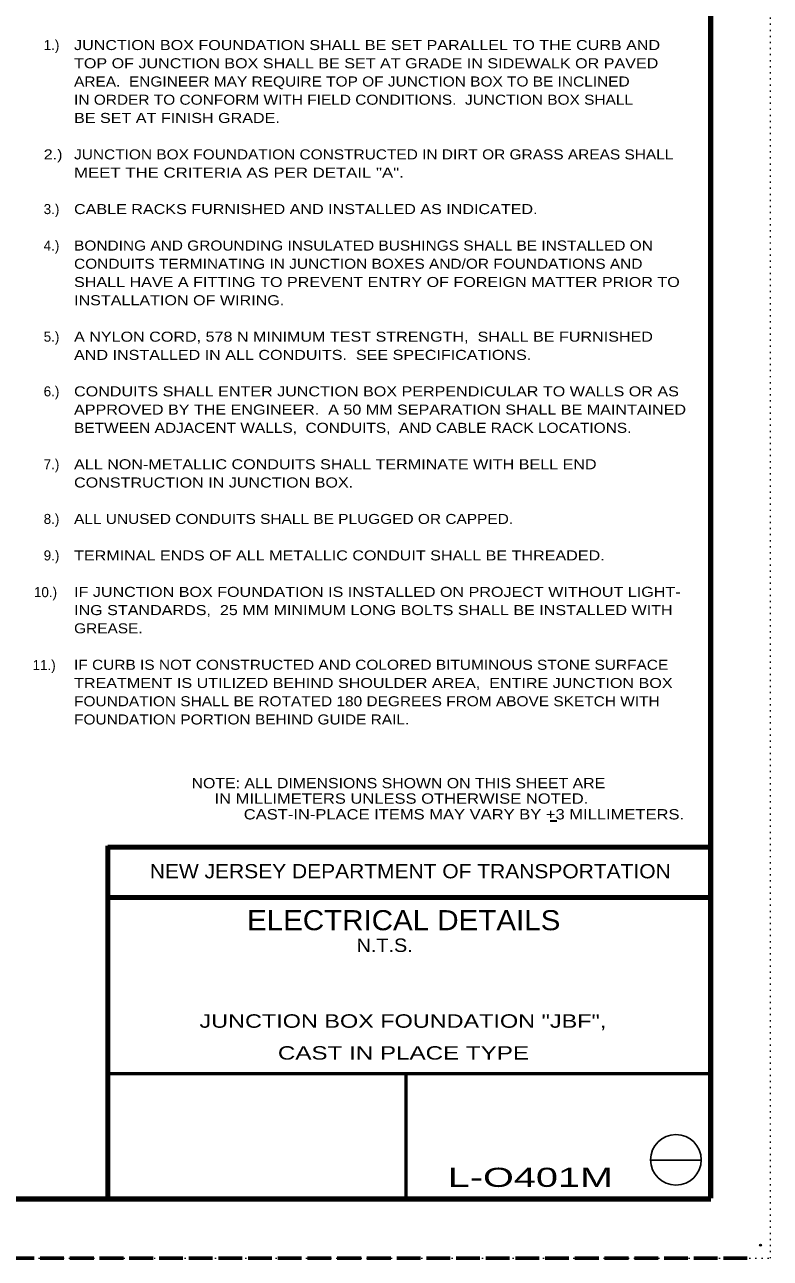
# Model space of a CAD drawing. Extents: x 312583 to 312854, y 144419 to 144597.
# Drawn here: x 312797 to 312853.5, y 144418.6 to 144512 of the extents above; entities that cross this region are included whole.
import ezdxf
from ezdxf.enums import TextEntityAlignment as Align

# ---------------------------------------------------------------- set-up
doc = ezdxf.new("R2010")
doc.units = 0
doc.header["$LTSCALE"] = 0.3
doc.header["$PDMODE"] = 32
doc.header["$PDSIZE"] = 0.15
doc.linetypes.add('DOTTED', pattern=[1.5, 0.3, -1.2])
doc.linetypes.add('LONG_DASHED', pattern=[7.5, 6, -1.5])
for name, color, linetype, lineweight in [('1', 7, 'Continuous', 13), ('10', 7, 'Continuous', 25), ('63', 7, 'DOTTED', 13)]:
    doc.layers.add(name, color=color, linetype=linetype, lineweight=lineweight)
doc.layers.add('2', color=7, linetype='Continuous')
doc.layers.add('5', color=7, linetype='Continuous')

msp = doc.modelspace()

# ---------------------------------------------------------------- linework, layer by layer
at = {"layer": '1', "lineweight": 158}
for p, q in [((312849, 144423.1446), (312849, 144585.0846)), ((312616.5, 144423.0846), (312849, 144423.0846))]:
    msp.add_line(p, q, dxfattribs=at)
at = {"layer": '1', "lineweight": 35}
msp.add_line((312836.8248, 144451.6973), (312837.3347, 144451.6973), dxfattribs=at)
at = {"layer": '1', "lineweight": 80}
for p, q in [((312803.31, 144423.1446), (312803.31, 144449.8146)), ((312803.31, 144449.7246), (312849, 144449.7246)), ((312803.31, 144445.9146), (312849, 144445.9146))]:
    msp.add_line(p, q, dxfattribs=at)
at = {"layer": '1', "lineweight": 53}
for p, q in [((312849, 144432.5546), (312803.2881, 144432.5546)), ((312825.881, 144432.5546), (312825.881, 144423.0843))]:
    msp.add_line(p, q, dxfattribs=at)
at = {"layer": '1', "linetype": 'LONG_DASHED', "lineweight": 60}
msp.add_line((312851.75, 144418.5846), (312583.526, 144418.5846), dxfattribs=at)
at = {"layer": '1'}
msp.add_point((312852.75, 144419.5846), dxfattribs=at)
at = {"layer": '10'}
msp.add_line((312844.4384, 144426.0259), (312848.2794, 144426.0259), dxfattribs=at)
msp.add_circle((312846.3494, 144426.0405), 1.9159, dxfattribs=at)
at = {"layer": '63'}
msp.add_lwpolyline([(312601.2, 144418.5846), (312853.5, 144418.5846), (312853.5, 144596.7846)], dxfattribs=at)

# ---------------------------------------------------------------- texts
at = {"layer": '1'}
for s, p in [('1.)', (312798.4647, 144510.0623)), ('3.)', (312798.4647, 144497.6423)), ('4.)', (312798.4647, 144494.8823)), ('5.)', (312798.4647, 144487.9823)), ('6.)', (312798.4647, 144483.8423)), ('7.)', (312798.4647, 144478.3223)), ('8.)', (312798.4647, 144474.1823)), ('9.)', (312798.4647, 144471.4223)), ('10.)', (312797.727, 144468.6412)), ('11.)', (312797.6216, 144463.1212))]:
    msp.add_text(s, height=0.76, dxfattribs=at).set_placement(p)
for s, height, width, p in [('AREA.  ENGINEER MAY REQUIRE TOP OF JUNCTION BOX TO BE INCLINED', 0.76, 1.15, (312800.7647, 144507.3023)), ('IN ORDER TO CONFORM WITH FIELD CONDITIONS.  JUNCTION BOX SHALL', 0.76, 1.15, (312800.7647, 144505.9223)), ('BE SET AT FINISH GRADE.', 0.76, 1.2, (312800.7647, 144504.5423)), ('2.)', 0.76, 1.2, (312798.4647, 144501.7823)), ('JUNCTION BOX FOUNDATION CONSTRUCTED IN DIRT OR GRASS AREAS SHALL', 0.76, 1.15, (312800.7647, 144501.7823)), ('MEET THE CRITERIA AS PER DETAIL "A".', 0.76, 1.25, (312800.7647, 144500.4023)), ('GREASE.  ', 0.76, 1.15, (312800.7647, 144465.9023)), ('NOTE: ALL DIMENSIONS SHOWN ON THIS SHEET ARE', 0.78, 1.15, (312809.6669, 144454.1725)), ('     IN MILLIMETERS UNLESS OTHERWISE NOTED.', 0.78, 1.2, (312809.6668, 144453.0025)), ('CAST-IN-PLACE ITEMS MAY VARY BY +3 MILLIMETERS.', 0.78, 1.2, (312813.6177, 144451.8116))]:
    msp.add_text(s, height=height, dxfattribs=dict(at, width=width)).set_placement(p)
at = {"layer": '1', "width": 1.1}
for s, height, p in [('NEW JERSEY DEPARTMENT OF TRANSPORTATION', 1.08, (312826.2285, 144447.3546)), ('ELECTRICAL DETAILS', 1.52, (312825.7303, 144443.4248))]:
    msp.add_text(s, height=height, dxfattribs=at).set_placement(p, align=Align.CENTER)
at = {"layer": '2'}
for s, width, p in [('JUNCTION BOX FOUNDATION SHALL BE SET PARALLEL TO THE CURB AND   ', 1.2, (312800.7647, 144510.0623)), ('TOP OF JUNCTION BOX SHALL BE SET AT GRADE IN SIDEWALK OR PAVED  ', 1.2, (312800.7647, 144508.6823)), ('CABLE RACKS FURNISHED AND INSTALLED AS INDICATED.  ', 1.2, (312800.7647, 144497.6423)), ('BONDING AND GROUNDING INSULATED BUSHINGS SHALL BE INSTALLED ON   ', 1.15, (312800.7647, 144494.8823)), ('CONDUITS TERMINATING IN JUNCTION BOXES AND/OR FOUNDATIONS AND   ', 1.15, (312800.7647, 144493.5023)), ('SHALL HAVE A FITTING TO PREVENT ENTRY OF FOREIGN MATTER PRIOR TO    ', 1.2, (312800.7647, 144492.1223)), ('INSTALLATION OF WIRING.   ', 1.2, (312800.7647, 144490.7423)), ('A NYLON CORD, 578 N MINIMUM TEST STRENGTH,  SHALL BE FURNISHED   ', 1.2, (312800.7647, 144487.9823)), ('AND INSTALLED IN ALL CONDUITS.  SEE SPECIFICATIONS.  ', 1.2, (312800.7647, 144486.6023)), ('CONDUITS SHALL ENTER JUNCTION BOX PERPENDICULAR TO WALLS OR AS    ', 1.2, (312800.7647, 144483.8423)), ('APPROVED BY THE ENGINEER.  A 50 MM SEPARATION SHALL BE MAINTAINED  ', 1.2, (312800.7647, 144482.4623)), ('BETWEEN ADJACENT WALLS,  CONDUITS,  AND CABLE RACK LOCATIONS.  ', 1.15, (312800.7647, 144481.0823)), ('ALL NON-METALLIC CONDUITS SHALL TERMINATE WITH BELL END     ', 1.2, (312800.7647, 144478.3223)), ('CONSTRUCTION IN JUNCTION BOX.   ', 1.2, (312800.7647, 144476.9423)), ('ALL UNUSED CONDUITS SHALL BE PLUGGED OR CAPPED.   ', 1.15, (312800.7647, 144474.1823)), ('TERMINAL ENDS OF ALL METALLIC CONDUIT SHALL BE THREADED.  ', 1.2, (312800.7647, 144471.4223)), ('IF JUNCTION BOX FOUNDATION IS INSTALLED ON PROJECT WITHOUT LIGHT-  ', 1.2, (312800.7647, 144468.6623)), ('ING STANDARDS,  25 MM MINIMUM LONG BOLTS SHALL BE INSTALLED WITH   ', 1.2, (312800.7647, 144467.2823)), ('IF CURB IS NOT CONSTRUCTED AND COLORED BITUMINOUS STONE SURFACE    ', 1.15, (312800.7647, 144463.1423)), ('TREATMENT IS UTILIZED BEHIND SHOULDER AREA,  ENTIRE JUNCTION BOX   ', 1.2, (312800.7647, 144461.7623)), ('FOUNDATION SHALL BE ROTATED 180 DEGREES FROM ABOVE SKETCH WITH   ', 1.15, (312800.7647, 144460.3823)), ('FOUNDATION PORTION BEHIND GUIDE RAIL.  ', 1.15, (312800.7647, 144459.0023))]:
    msp.add_text(s, height=0.76, dxfattribs=dict(at, width=width)).set_placement(p)
for s, height, width, p in [('    N.T.S.  ', 1.02, 1.1, (312823.87, 144441.778)), ('         JUNCTION BOX FOUNDATION "JBF",          ', 1.02, 1.3, (312825.918, 144436.0399)), ('          CAST IN PLACE TYPE          ', 1.014, 1.35, (312825.7135, 144433.6297))]:
    msp.add_text(s, height=height, dxfattribs=dict(at, width=width)).set_placement(p, align=Align.CENTER)
at = {"layer": '5', "width": 1.55}
msp.add_text('L-O401M   ', height=1.449, dxfattribs=at).set_placement((312836.5768, 144423.9917), align=Align.CENTER)

doc.saveas('drawing.dxf')
